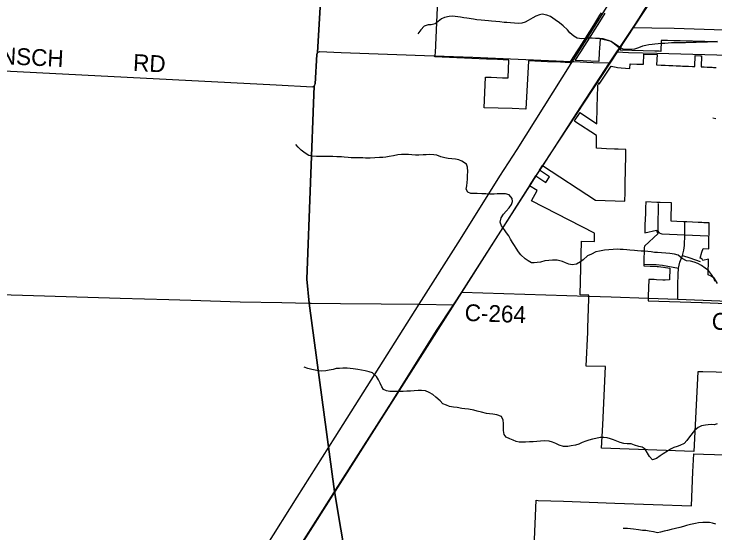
# Model space of a CAD drawing. Extents: x 114604 to 551442, y 316898 to 567001.
# Drawn here: x 166736 to 179238, y 345598 to 354850 of the extents above; entities that cross this region are included whole.
import ezdxf

# ---------------------------------------------------------------- set-up
doc = ezdxf.new("R2010")
doc.units = 0
for name, color, linetype in [('_CIVIL_CONSTRUCTION', 7, 'Continuous'), ('GE_P_Alignment_1000_Bearings', 7, 'Continuous'), ('GE_P_Alignment_1000_Cardinal_Points', 7, 'Continuous'), ('GE_P_Alignment_1000_Stations', 7, 'Continuous'), ('GE_P_Alignment_100_Stations', 7, 'Continuous'), ('GE_P_Alignment_500_Bearings', 7, 'Continuous'), ('GE_P_Alignment_500_Distances', 7, 'Continuous'), ('PM_P_Cells', 7, 'Continuous'), ('PM_P_CL_Double_Solid', 7, 'Continuous')]:
    doc.layers.add(name, color=color, linetype=linetype)

msp = doc.modelspace()

# ---------------------------------------------------------------- linework, layer by layer
at = {"layer": '_CIVIL_CONSTRUCTION'}
for p, q in [((177780, 354610), (177892, 354784)), ((177516, 354217), (177780, 354610)), ((177354, 353980), (177490, 354177)), ((177490, 354177), (177516, 354217)), ((176063, 351983), (176120, 352072)), ((176120, 352072), (176178, 352161)), ((175949, 351805), (176063, 351983)), ((174573, 349668), (174723, 349890))]:
    msp.add_line(p, q, dxfattribs=at)
for points in [[(177892, 354784), (177989, 354936), (178405, 355564)], [(176178, 352161), (176766, 353077), (177354, 353980)], [(174723, 349890), (174847, 350089), (175949, 351805)], [(172441, 346316), (172453, 346334), (172471, 346363), (173478, 347939), (174269, 349208), (174573, 349668)], [(170917, 343893), (171073, 344163), (172441, 346316)]]:
    msp.add_lwpolyline(points, dxfattribs=at)
at = {"layer": 'GE_P_Alignment_1000_Bearings'}
for points in [[(196042, 380964), (194033, 377563), (193868, 377325), (192058, 375431), (190340, 374235), (188290, 370932), (187383, 369296), (186211, 367714), (185191, 366327), (183802, 363991), (182496, 361740), (179755, 357653), (178698, 356015), (176027, 351942), (171808, 345313), (170010, 342459), (166009, 336034), (165560, 335288), (165458, 335042), (165305, 334516), (164243, 330883)], [(165560, 336379), (167342, 339200), (168589, 341173), (170215, 343741), (170545, 344266), (170658, 344443), (170753, 344594), (171071, 345103), (171658, 346027), (171787, 346235), (172464, 347303), (173962, 349676), (174698, 350836), (175401, 351957), (175709, 352436), (176672, 353966), (176952, 354405), (177651, 355520)]]:
    msp.add_lwpolyline(points, dxfattribs=at)
at = {"layer": 'GE_P_Alignment_1000_Cardinal_Points'}
for points in [[(177780, 354610), (178111, 354605), (178510, 354597), (179757, 354559), (181276, 354507), (181313, 354506)], [(177490, 354177), (177594, 354169), (177697, 354166), (178202, 354155), (179699, 354109), (180360, 354086), (181479, 354052), (181495, 354052)], [(178222, 351472), (178216, 351047), (178220, 350992), (178229, 350966), (178254, 350943), (178290, 350929), (178698, 350915), (179108, 350896)], [(178575, 349766), (178574, 350028), (178579, 350207), (178590, 350317), (178612, 350425), (178657, 350547), (178685, 350637), (178693, 350723), (178698, 350915), (178702, 351131)], [(178657, 350547), (178788, 350504), (178972, 350438)], [(177975, 350389), (178190, 350386), (178302, 350374), (178397, 350354), (178590, 350317)]]:
    msp.add_lwpolyline(points, dxfattribs=at)
at = {"layer": 'GE_P_Alignment_1000_Stations'}
for p, q in [((177780, 354610), (177892, 354784)), ((177516, 354217), (177780, 354610)), ((177354, 353980), (177490, 354177)), ((177490, 354177), (177516, 354217)), ((176063, 351983), (176120, 352072)), ((176120, 352072), (176178, 352161)), ((175949, 351805), (176063, 351983)), ((174573, 349668), (174723, 349890))]:
    msp.add_line(p, q, dxfattribs=at)
for points in [[(177892, 354784), (177989, 354936), (178405, 355564)], [(176178, 352161), (176766, 353077), (177354, 353980)], [(174723, 349890), (174847, 350089), (175949, 351805)], [(172441, 346316), (172453, 346334), (172471, 346363), (173478, 347939), (174269, 349208), (174573, 349668)], [(170917, 343893), (171073, 344163), (172441, 346316)]]:
    msp.add_lwpolyline(points, dxfattribs=at)
at = {"layer": 'GE_P_Alignment_100_Stations'}
for points in [[(177209, 354872), (177181, 354828), (177144, 354769), (177107, 354710), (177069, 354651), (176928, 354427), (176814, 354246), (176769, 354175), (176674, 354025), (176656, 353996), (176646, 353981), (176481, 353989), (176253, 353999), (175912, 354013), (175867, 353154), (175620, 353163), (175121, 353180), (175147, 353725), (175245, 353722), (175346, 353718), (175448, 353714), (175549, 353710), (175563, 354030), (175462, 354034), (175362, 354039), (175261, 354043), (175162, 354048), (174243, 354085), (174244, 354094), (174247, 354124), (174251, 354157), (174294, 355109)], [(179282, 354351), (179170, 354354), (179058, 354358), (179003, 354360), (178979, 354360), (178946, 354361), (178839, 354364), (178726, 354368), (178615, 354371), (178503, 354374), (178390, 354377), (178280, 354380), (178273, 354185), (178243, 354186), (178163, 354188), (177547, 354206), (177559, 354225), (177506, 354267), (177501, 354271), (177386, 354360), (177189, 354408), (177178, 354237), (177175, 354178), (177167, 354003), (176745, 354022), (176845, 354176), (177212, 354760), (177279, 354867)], [(180694, 348429), (179021, 348470), (178932, 348473), (178862, 347049), (177217, 347111), (177236, 347525), (177283, 348564), (176943, 348574), (176969, 349176), (176972, 349258), (176989, 349771), (176990, 349791), (176991, 349821), (176991, 349840), (176835, 349846), (176860, 350803), (177087, 350796), (177091, 350946), (177091, 350946), (175966, 351521), (176068, 351705), (175931, 351787), (176045, 351965), (176221, 351849), (176285, 351948), (176106, 352064), (176159, 352149), (177107, 351532), (177107, 351532), (177631, 351513), (177634, 351670), (177634, 351681), (177636, 351750), (177637, 351830), (177639, 351909), (177641, 351989), (177643, 352069), (177644, 352149), (177646, 352249), (177649, 352358), (177650, 352433), (177509, 352439), (177449, 352442), (177303, 352449), (177213, 352453), (177123, 352457), (177126, 352685), (176741, 352937), (176733, 352943), (176831, 353094), (176840, 353088), (177129, 352895), (177132, 353004), (177134, 353075), (177137, 353214), (177140, 353358), (177146, 353583), (177175, 353629), (177174, 353597), (177386, 353920), (177478, 353900), (177502, 353894), (177563, 353890), (177722, 353878), (177723, 353961), (177844, 353959), (177950, 353954), (177962, 353954), (177972, 354137), (178207, 354130), (178196, 353944), (178207, 353943), (178277, 353940), (178313, 353939), (178347, 353937), (178417, 353934), (178430, 353933), (178487, 353931), (178546, 353928), (178556, 353928), (178626, 353925), (178659, 353923), (178696, 353922), (178767, 353919), (178836, 353916), (178880, 353914), (178887, 354109), (178980, 354106), (178998, 354106), (178991, 353909), (179048, 353906), (179101, 353904), (179119, 353903), (179190, 353900), (179211, 353899), (179261, 353897)], [(179285, 350048), (179228, 350137), (179171, 350175), (179116, 350203), (179122, 350480), (179021, 350458), (179007, 350482), (178991, 350492), (178971, 350496), (179006, 350603), (179028, 350669), (179126, 350665), (179130, 350866), (179132, 350926), (179136, 351126), (179038, 351130), (179002, 351132), (178938, 351134), (178838, 351139), (178736, 351143), (178674, 351146), (178555, 351151), (178455, 351155), (178456, 351180), (178459, 351280), (178462, 351381), (178464, 351481), (178261, 351489), (178201, 351491), (178002, 351499), (177999, 351395), (177996, 351295), (177993, 351194), (177990, 351094), (177986, 350950), (178193, 350997), (178204, 350965), (178225, 350940), (177979, 350712), (177978, 350682), (177970, 350421), (177969, 350362), (178085, 350357), (178183, 350353), (178205, 350351), (178228, 350349), (178273, 350344), (178319, 350337), (178435, 350318), (178427, 350109), (178352, 350108), (178310, 350107), (178193, 350112), (178153, 350114), (178077, 350117), (178057, 350118), (178048, 349817), (178048, 349787), (178045, 349737), (178995, 349707), (179012, 349706), (179439, 349688)], [(179275, 342723), (177612, 342905), (177613, 342924), (177614, 342934), (177626, 343122), (177526, 343132), (177427, 343143), (177414, 342926), (177315, 342937), (176560, 343017), (176441, 343031), (175995, 343083), (175916, 343092), (175961, 344168), (175981, 344637), (176046, 346180), (176083, 346179), (176537, 346164), (177452, 346131), (178821, 346082), (178845, 346689), (178861, 347009), (179032, 347004), (180208, 346966)]]:
    msp.add_lwpolyline(points, dxfattribs=at)
at = {"layer": 'GE_P_Alignment_500_Bearings'}
msp.add_line((174573, 349668), (174723, 349890), dxfattribs=at)
for points in [[(165285, 353903), (171410, 353589), (172060, 353554), (172093, 353569), (172106, 353604), (172140, 354125), (172151, 354163), (172179, 354179)], [(172179, 354179), (172184, 354182), (172570, 354163), (174226, 354105), (174236, 354105)], [(174236, 354105), (174917, 354081), (176675, 354006), (176718, 354004)], [(176718, 354004), (177067, 353987), (177354, 353980)], [(165163, 349894), (166286, 349855), (167279, 349825), (168631, 349785), (169499, 349762), (169890, 349748), (170770, 349721), (171512, 349704), (172003, 349694), (172034, 349694)], [(174723, 349890), (176972, 349819), (176993, 349818)], [(176993, 349818), (177387, 349806), (178046, 349783)], [(172034, 349694), (172562, 349692), (173285, 349686), (173965, 349676), (174573, 349668)], [(178046, 349783), (178575, 349766), (179326, 349737), (179596, 349725), (180130, 349701)]]:
    msp.add_lwpolyline(points, dxfattribs=at)
at = {"layer": 'GE_P_Alignment_500_Distances'}
for points in [[(172473, 332991), (172677, 336606), (172727, 337511), (172727, 337514), (172753, 337899), (172759, 338018), (172778, 338411), (172978, 342712), (172954, 342875), (172863, 343417), (172681, 344992), (172451, 346337), (172001, 349697), (171956, 350122), (172091, 353572), (172105, 353607), (172139, 354128), (172150, 354165), (172368, 357901)], [(172368, 357901), (172150, 354165), (172139, 354128), (172105, 353607), (172091, 353572), (171956, 350122), (172001, 349697), (172451, 346337), (172681, 344992), (172863, 343417), (172954, 342875), (172978, 342712), (172778, 338411), (172759, 338018), (172753, 337899), (172727, 337514), (172727, 337511), (172677, 336606), (172473, 332991)]]:
    msp.add_lwpolyline(points, dxfattribs=at)
at = {"layer": 'PM_P_Cells'}
for points in [[(176158, 354846), (176106, 354838), (176042, 354812), (175991, 354782), (175907, 354732), (175853, 354706), (175793, 354690), (175725, 354684), (175665, 354688), (175591, 354694), (175527, 354700), (175477, 354702), (175401, 354709), (175329, 354715), (175251, 354723), (175197, 354729), (175133, 354735), (175069, 354739), (174989, 354749), (174933, 354759), (174813, 354775), (174761, 354782), (174701, 354792), (174605, 354806), (174551, 354812), (174496, 354806), (174416, 354786), (174360, 354764), (174302, 354718), (174250, 354676), (174178, 354656), (174122, 354658), (174054, 354636), (173990, 354570), (173938, 354500)], [(179283, 354359), (179227, 354353), (179163, 354353), (179105, 354351), (179053, 354351), (178975, 354347), (178901, 354341), (178847, 354341), (178715, 354337), (178577, 354338), (178515, 354336), (178465, 354334), (178404, 354332), (178344, 354326), (178284, 354322), (178222, 354316), (178166, 354312), (178116, 354308), (178060, 354302), (178006, 354292), (177944, 354276), (177876, 354250), (177800, 354224), (177724, 354219), (177662, 354217), (177600, 354223), (177548, 354253), (177484, 354295), (177420, 354335), (177358, 354373), (177300, 354391), (177242, 354406), (177176, 354412), (177108, 354416), (177046, 354418), (176980, 354418), (176916, 354412), (176866, 354406), (176781, 354422), (176721, 354454), (176652, 354515), (176606, 354569), (176530, 354641), (176466, 354691), (176388, 354747), (176302, 354804), (176242, 354832), (176158, 354846)], [(179251, 352982), (179199, 352992)], [(174088, 352342), (174036, 352338), (173954, 352332), (173894, 352336), (173834, 352342), (173772, 352348), (173722, 352346), (173648, 352344), (173580, 352340), (173504, 352322), (173428, 352308), (173366, 352301), (173312, 352295), (173252, 352291), (173172, 352287), (173090, 352283), (173006, 352283), (172956, 352285), (172860, 352285), (172801, 352287), (172751, 352289), (172693, 352293), (172627, 352299), (172575, 352304), (172491, 352306), (172421, 352308), (172357, 352310), (172291, 352308), (172209, 352308), (172129, 352310), (172053, 352314), (171997, 352326), (171927, 352367), (171855, 352421), (171805, 352475), (171763, 352525)], [(179209, 350152), (179177, 350207), (179121, 350279), (179063, 350321), (178997, 350369), (178933, 350401), (178865, 350427), (178801, 350442), (178731, 350448), (178655, 350494), (178581, 350548), (178515, 350566), (178435, 350578), (178363, 350586), (178283, 350593), (178213, 350599), (178161, 350601), (178099, 350611), (178043, 350615), (177977, 350621), (177922, 350623), (177856, 350631), (177800, 350635), (177722, 350639), (177668, 350644), (177602, 350650), (177550, 350652), (177492, 350656), (177424, 350654), (177346, 350648), (177268, 350638), (177180, 350624), (177114, 350608), (177034, 350570), (176964, 350536), (176890, 350466), (176839, 350434), (176769, 350392), (176691, 350378), (176631, 350392), (176573, 350413), (176519, 350435), (176425, 350459), (176341, 350463), (176273, 350455), (176201, 350447), (176129, 350427), (176069, 350421), (176015, 350415), (175963, 350415), (175909, 350447), (175851, 350484), (175773, 350556), (175733, 350610), (175691, 350676), (175665, 350726), (175625, 350779), (175593, 350837), (175563, 350893), (175521, 350951), (175485, 351001), (175431, 351075), (175406, 351142), (175424, 351218), (175468, 351282), (175516, 351334), (175566, 351396), (175608, 351456), (175626, 351508), (175620, 351562), (175566, 351624), (175502, 351644), (175420, 351646), (175354, 351645), (175302, 351641), (175214, 351641), (175154, 351643), (175078, 351647), (174996, 351649), (174938, 351649), (174884, 351653), (174828, 351673), (174802, 351729), (174812, 351788), (174820, 351846), (174826, 351908), (174826, 351972), (174828, 352044), (174825, 352120), (174805, 352172), (174725, 352229), (174671, 352249), (174609, 352263), (174547, 352269), (174479, 352277), (174421, 352289), (174349, 352303), (174279, 352331), (174223, 352341), (174154, 352344), (174088, 352342)], [(179241, 350080), (179209, 350152)], [(172866, 348510), (172786, 348524), (172734, 348530), (172678, 348534), (172602, 348536), (172540, 348532), (172484, 348528), (172427, 348514), (172355, 348500), (172295, 348490), (172225, 348484), (172167, 348491), (172107, 348501), (172049, 348511), (171979, 348531), (171913, 348553)], [(178874, 347426), (178782, 347313), (178738, 347247), (178688, 347195), (178614, 347155), (178564, 347137), (178504, 347119), (178445, 347093), (178393, 347059), (178313, 347009), (178261, 346971), (178193, 346923), (178123, 346901), (178069, 346960), (177993, 347092), (177939, 347130), (177879, 347140), (177801, 347166), (177745, 347185), (177669, 347189), (177613, 347191), (177545, 347211), (177487, 347235), (177429, 347261), (177377, 347279), (177315, 347291), (177253, 347301), (177193, 347302), (177115, 347284), (177051, 347270), (176991, 347254), (176933, 347236), (176869, 347208), (176808, 347182), (176748, 347166), (176674, 347150), (176612, 347142), (176536, 347142), (176458, 347166), (176400, 347190), (176340, 347218), (176278, 347237), (176206, 347243), (176128, 347237), (176058, 347229), (175996, 347223), (175932, 347221), (175858, 347217), (175808, 347217), (175744, 347219), (175690, 347229), (175636, 347251), (175580, 347274), (175512, 347304), (175478, 347356), (175464, 347426), (175466, 347494), (175466, 347552), (175460, 347608), (175432, 347675), (175350, 347703), (175276, 347717), (175216, 347723), (175164, 347729), (175076, 347749), (174996, 347769), (174940, 347785), (174844, 347804), (174776, 347810), (174724, 347818), (174640, 347832), (174574, 347842), (174504, 347854), (174450, 347874), (174386, 347902), (174334, 347951), (174260, 348021), (174206, 348065), (174142, 348103), (174074, 348131), (174006, 348139), (173946, 348135), (173874, 348130), (173810, 348126), (173742, 348124), (173676, 348122), (173620, 348122), (173566, 348120), (173506, 348120), (173440, 348122), (173378, 348130), (173324, 348154), (173296, 348204), (173264, 348271), (173236, 348327), (173204, 348387), (173128, 348451), (173072, 348473), (173002, 348487), (172932, 348498), (172866, 348510)], [(179277, 347543), (179223, 347527), (179171, 347529), (179117, 347527), (179067, 347521), (179000, 347506), (178936, 347476), (178874, 347426)], [(178455, 345659), (178389, 345643), (178333, 345629), (178267, 345611), (178215, 345601), (178139, 345615), (178067, 345629), (178003, 345639), (177947, 345643), (177875, 345655), (177783, 345667), (177729, 345674), (177675, 345676), (177603, 345676)], [(179252, 345756), (179192, 345774), (179140, 345782), (179086, 345784), (179020, 345782), (178946, 345778), (178890, 345766), (178802, 345748), (178730, 345728), (178678, 345712), (178611, 345694), (178535, 345676), (178455, 345659)]]:
    msp.add_lwpolyline(points, dxfattribs=at)

# ---------------------------------------------------------------- texts
at = {"layer": 'PM_P_CL_Double_Solid'}
for s, rotation, p in [('RENSCH', 357.0977, (165922, 353989)), ('RD', 356.9592, (168854, 353838)), ('C-264', 357.9354, (174770, 349379)), ('C-264', 357.6876, (179175, 349226))]:
    msp.add_text(s, height=300, rotation=rotation, dxfattribs=at).set_placement(p)

doc.saveas('drawing.dxf')
